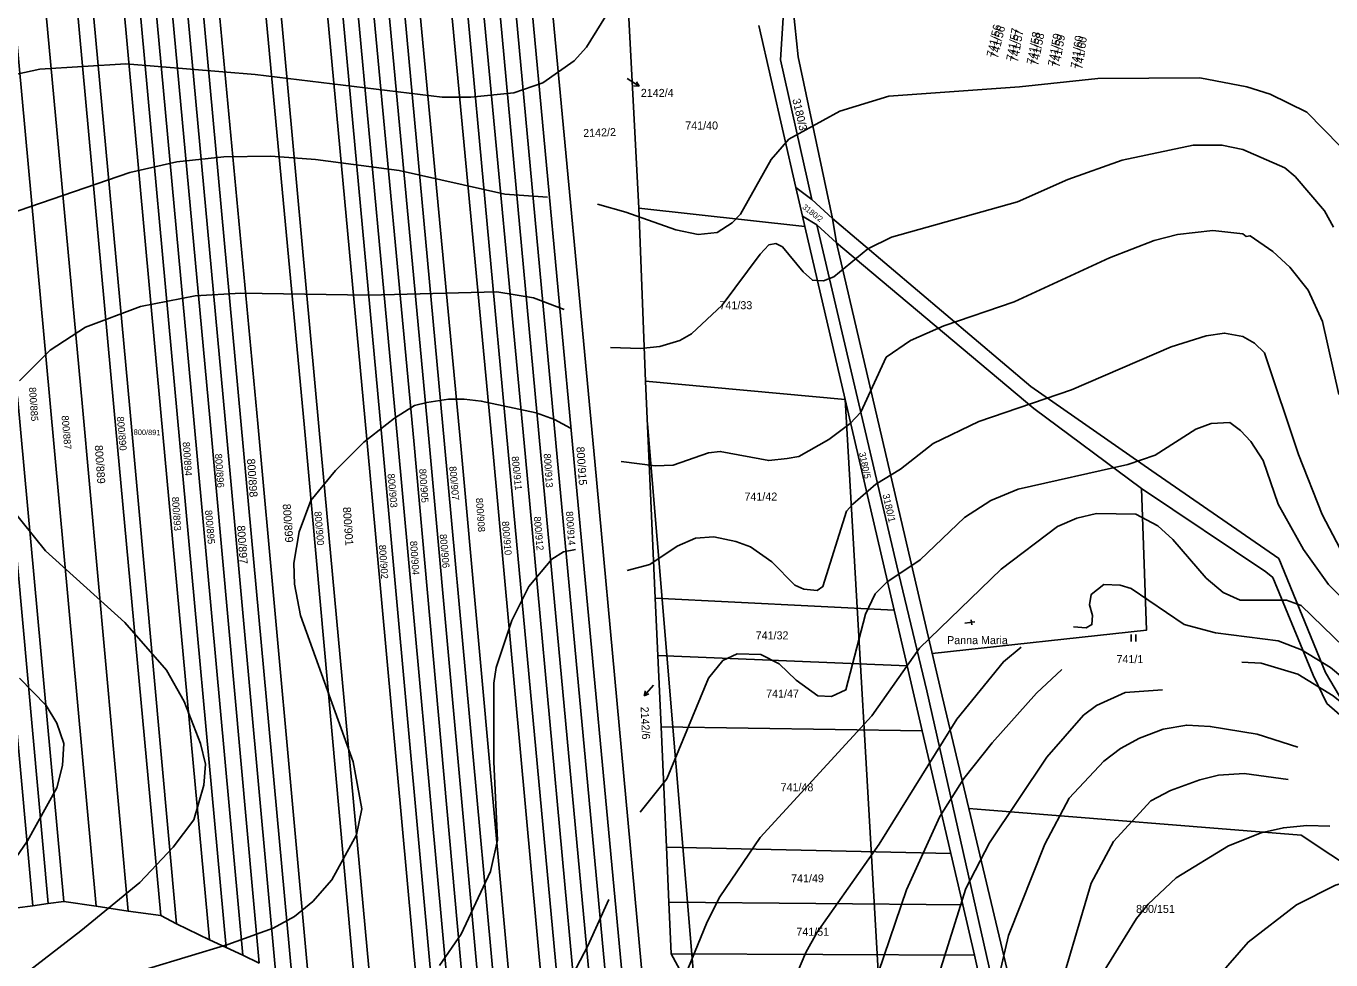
# Model space of a CAD drawing. Extents: x -555860 to -552701, y -1187050 to -1182291.
# Drawn here: x -554447.8 to -554170.8, y -1185774.2 to -1185576 of the extents above; entities that cross this region are included whole.
import ezdxf

# ---------------------------------------------------------------- set-up
doc = ezdxf.new("R2010")
doc.units = 0
for name, color, linetype in [('LEG_2b', 7, 'Continuous'), ('Level 16', 7, 'Continuous'), ('Level 25', 7, 'Continuous'), ('Level 40', 7, 'Continuous'), ('Level 41', 7, 'Continuous'), ('navrh_BV', 7, 'Continuous'), ('Poz předměty', 7, 'Continuous')]:
    doc.layers.add(name, color=color, linetype=linetype)

msp = doc.modelspace()

# ---------------------------------------------------------------- linework, layer by layer
at = {"layer": 'Level 16'}
for p, q in [((-554320.16, -1185587.15), (-554317.65, -1185588.79)), ((-554317.65, -1185588.79), (-554318.21, -1185587.83)), ((-554317.65, -1185588.79), (-554318.76, -1185588.66)), ((-554314.61, -1185715.92), (-554316.57, -1185718.19)), ((-554316.57, -1185718.19), (-554316.3, -1185717.11)), ((-554316.57, -1185718.19), (-554315.54, -1185717.76))]:
    msp.add_line(p, q, dxfattribs=at)
at = {"layer": 'Level 25'}
for p, q in [((-554247.16, -1185702.02), (-554247.02, -1185703.06)), ((-554246.4, -1185702.45), (-554248.48, -1185702.72)), ((-554213.2, -1185706.64), (-554213.2, -1185705.14)), ((-554212.2, -1185706.64), (-554212.2, -1185705.14))]:
    msp.add_line(p, q, dxfattribs=at)
at = {"layer": 'Level 40'}
for points in [[(-554326.49, -1185613.8), (-554320.45, -1185615.5), (-554309.82, -1185619.27), (-554305.11, -1185620.24), (-554301.08, -1185619.8), (-554297.9, -1185617.75), (-554296.1, -1185615.94), (-554289.58, -1185604.3), (-554285.84, -1185600), (-554275.02, -1185594.04), (-554264.62, -1185590.85), (-554236.89, -1185588.91), (-554220.25, -1185587.1), (-554198.62, -1185586.96), (-554188.64, -1185588.91), (-554183.65, -1185590.43), (-554175.88, -1185594.31), (-554168.81, -1185601.52)], [(-554456.52, -1185617.61), (-554425.74, -1185607.07), (-554415.76, -1185604.85), (-554405.77, -1185603.74), (-554395.79, -1185603.6), (-554386.36, -1185604.3), (-554368.61, -1185606.66), (-554346.15, -1185611.65), (-554337.11, -1185612.31)], [(-554165.62, -1185710.09), (-554177.12, -1185699), (-554180.18, -1185697.89), (-554190.02, -1185697.89), (-554193.63, -1185696.23), (-554197.23, -1185693.18), (-554204.31, -1185685), (-554207.49, -1185682.08), (-554212.21, -1185679.59), (-554220.53, -1185679.45), (-554224.69, -1185680.42), (-554228.85, -1185682.22), (-554240.77, -1185691.24), (-554258.1, -1185708.01), (-554268.23, -1185722.43), (-554291.94, -1185748.22), (-554300.53, -1185760.84), (-554303.17, -1185766.11), (-554310.64, -1185784.29)], [(-554451.67, -1185755.02), (-554447.51, -1185748.92), (-554441.27, -1185737.69), (-554440.02, -1185732.97), (-554439.74, -1185728.26), (-554441.27, -1185723.96), (-554443.49, -1185720.22), (-554449.17, -1185714.39)], [(-554233.48, -1185802.27), (-554229.54, -1185784.55), (-554221.64, -1185757.93), (-554216.92, -1185749.06), (-554209.02, -1185740.46), (-554204.82, -1185738.24), (-554198.62, -1185736.02), (-554194.67, -1185735.02), (-554189.19, -1185734.63), (-554179.85, -1185735.92)]]:
    msp.add_lwpolyline(points, dxfattribs=at)
at = {"layer": 'Level 41'}
for points in [[(-554454.03, -1185587.1), (-554444.88, -1185585.16), (-554426.57, -1185584.05), (-554399.12, -1185586.27), (-554359.46, -1185591.12), (-554353.36, -1185591.12), (-554344.21, -1185590.15), (-554338.11, -1185588.07), (-554331.45, -1185583.36), (-554328.82, -1185580.45), (-554321.64, -1185568.86)], [(-554323.69, -1185644.21), (-554317.32, -1185644.47), (-554313.21, -1185644.05), (-554308.99, -1185642.71), (-554306.49, -1185641.32), (-554299.98, -1185635.22), (-554291.94, -1185624.4), (-554290.13, -1185622.46), (-554288.61, -1185622.18), (-554287.22, -1185622.88), (-554282.79, -1185628.15), (-554280.84, -1185629.95), (-554278.49, -1185630.09), (-554276.27, -1185629.26), (-554269.06, -1185623.29), (-554264.07, -1185620.8), (-554237.31, -1185613.31), (-554226.63, -1185608.6), (-554215.12, -1185604.44), (-554200.01, -1185601.25), (-554193.91, -1185601.25), (-554189.47, -1185602.22), (-554180.59, -1185606.1), (-554178.38, -1185607.9), (-554172.14, -1185615.25), (-554170.2, -1185618.72)], [(-554169.09, -1185654.21), (-554172.55, -1185638.68), (-554175.6, -1185632.03), (-554179.48, -1185627.18), (-554183.09, -1185623.85), (-554187.94, -1185620.52), (-554188.78, -1185620.66), (-554189.47, -1185620.1), (-554195.85, -1185619.41), (-554203.33, -1185620.24), (-554208.33, -1185621.49), (-554217.76, -1185625.23), (-554238, -1185634.52), (-554252.97, -1185639.66), (-554260.05, -1185642.71), (-554265.18, -1185646.31), (-554270.58, -1185657.96), (-554272.86, -1185660.39), (-554277.38, -1185663.78), (-554283.76, -1185667.39), (-554286.23, -1185667.81), (-554290.13, -1185668.22), (-554300.4, -1185666.28), (-554302.89, -1185666.55), (-554310.38, -1185669.19), (-554314.26, -1185669.33), (-554321.46, -1185668.45)], [(-554333.54, -1185636.15), (-554340.05, -1185633.69), (-554347.82, -1185632.44), (-554374.99, -1185633.14), (-554402.17, -1185632.72), (-554411.88, -1185633.28), (-554423.52, -1185635.5), (-554435.17, -1185639.93), (-554442.66, -1185644.78), (-554449.17, -1185651.3)], [(-554168.81, -1185686.94), (-554172.66, -1185679.69), (-554177.68, -1185666.97), (-554184.89, -1185645.34), (-554187.02, -1185643.31), (-554189.47, -1185641.87), (-554193.35, -1185641.18), (-554197.23, -1185641.74), (-554204.72, -1185644.09), (-554225.88, -1185653.21), (-554245.49, -1185659.9), (-554255.19, -1185664.61), (-554262.12, -1185670.02), (-554267.39, -1185673.21), (-554272.25, -1185677.51), (-554273.61, -1185678.95), (-554278.62, -1185694.98), (-554279.87, -1185695.81), (-554282.65, -1185695.53), (-554284.59, -1185694.7), (-554289.44, -1185689.71), (-554294.02, -1185686.52), (-554297.12, -1185685.39), (-554301.78, -1185684.44), (-554305.66, -1185684.72), (-554309.55, -1185686.38), (-554315.37, -1185690.27), (-554320.15, -1185691.59)], [(-554430.18, -1185778.59), (-554404.94, -1185770.96), (-554395.32, -1185767.45), (-554390.8, -1185765), (-554386.92, -1185761.81), (-554382.9, -1185757.24), (-554377.63, -1185747.67), (-554376.52, -1185742.12), (-554378.32, -1185732.14), (-554389.55, -1185701.08), (-554390.8, -1185694.43), (-554390.94, -1185689.99), (-554389.83, -1185683.33), (-554387.33, -1185676.68), (-554382.06, -1185670.3), (-554376.1, -1185664.34), (-554369.58, -1185659.21), (-554365.29, -1185656.57), (-554362.72, -1185655.93), (-554358.08, -1185655.18), (-554354.8, -1185655.19), (-554351.14, -1185655.6), (-554339.5, -1185658.1), (-554335.61, -1185659.48), (-554332.18, -1185661.37)], [(-554161.04, -1185704.96), (-554171.31, -1185694.56), (-554176.57, -1185687.07), (-554181.98, -1185677.51), (-554185.17, -1185668.22), (-554187.81, -1185664.2), (-554189.99, -1185661.87), (-554192.24, -1185660.18), (-554196.18, -1185660.39), (-554199.45, -1185661.56), (-554208.05, -1185667.11), (-554213.87, -1185669.05), (-554237.17, -1185674.32), (-554242.99, -1185676.68), (-554248.54, -1185680.28), (-554257.97, -1185689.29), (-554265.04, -1185694.01), (-554267.53, -1185696.5), (-554269.61, -1185700.8), (-554273.77, -1185716.89), (-554276.82, -1185718.27), (-554279.73, -1185718.13), (-554284.31, -1185714.81), (-554287.92, -1185711.34), (-554291.8, -1185709.4), (-554296.79, -1185709.26), (-554299.84, -1185710.65), (-554302.89, -1185714.39), (-554311.76, -1185735.75), (-554317.45, -1185742.82)], [(-554450.98, -1185678.34), (-554443.63, -1185687.35), (-554426.85, -1185702.61), (-554417.98, -1185712.73), (-554414.23, -1185719.38), (-554410.77, -1185728.26), (-554409.66, -1185732.69), (-554410.07, -1185737.13), (-554412.15, -1185744.48), (-554416.59, -1185750.3), (-554423.66, -1185757.79), (-554436.14, -1185768.05), (-554461.79, -1185787.74)], [(-554331.15, -1185687.12), (-554333.67, -1185687.63), (-554336.17, -1185689.16), (-554341.02, -1185694.98), (-554344.63, -1185702.19), (-554347.95, -1185712.17), (-554348.51, -1185715.5), (-554348.51, -1185732.14), (-554347.68, -1185748.78), (-554349.2, -1185755.43), (-554355.44, -1185768.75), (-554360.02, -1185775.4)], [(-554225.39, -1185703.49), (-554222.75, -1185703.71), (-554221.5, -1185703.02), (-554221.36, -1185701.08), (-554222.05, -1185698.86), (-554221.64, -1185696.64), (-554219, -1185694.56), (-554215.54, -1185694.7), (-554213.18, -1185695.39), (-554201.95, -1185703.02), (-554195.29, -1185704.82), (-554181.98, -1185706.49), (-554176.99, -1185708.43), (-554170.89, -1185712.17), (-554162.98, -1185718.69)], [(-554236.51, -1185707.81), (-554240.31, -1185710.91), (-554250.2, -1185723.13), (-554266.7, -1185749.61), (-554279.87, -1185768.33), (-554282.25, -1185772.64), (-554284.03, -1185776.79), (-554287.08, -1185788.43), (-554288.05, -1185795.16), (-554290.41, -1185803.96), (-554297, -1185815.68)], [(-554271.14, -1185791.98), (-554266.84, -1185776.79), (-554260.88, -1185759.32), (-554253.81, -1185743.79), (-554248.68, -1185735.74), (-554242.71, -1185728.12), (-554233.29, -1185717.58), (-554227.88, -1185712.59)], [(-554094.33, -1185743.24), (-554110.16, -1185742.82), (-554130.12, -1185740.32), (-554136, -1185738.98), (-554140.11, -1185737.41), (-554162.43, -1185724.51), (-554170.33, -1185718.13), (-554177.82, -1185713.56), (-554185.59, -1185711.2), (-554189.67, -1185711.01)], [(-554257.85, -1185812.51), (-554256.58, -1185791.48), (-554254.36, -1185778.45), (-554248.26, -1185759.04), (-554243.27, -1185749.33), (-554231.07, -1185731.17), (-554223.3, -1185722.29), (-554220.53, -1185720.21), (-554214.43, -1185717.44), (-554206.52, -1185716.89)], [(-554177.81, -1185729.05), (-554186.42, -1185726.32), (-554196.4, -1185724.65), (-554201.39, -1185724.37), (-554206.39, -1185725.21), (-554211.38, -1185727.15), (-554215.46, -1185729.33), (-554219, -1185732), (-554226.35, -1185739.9), (-554231.48, -1185749.61), (-554239.25, -1185769.02), (-554242.85, -1185784.55), (-554243.96, -1185802.02), (-554242.44, -1185811.73), (-554240.38, -1185821.13)], [(-554171, -1185745.81), (-554175.86, -1185745.67), (-554180.87, -1185746.14), (-554185.59, -1185747.25), (-554192.52, -1185750.03), (-554203.61, -1185756.82), (-554209.57, -1185762.37), (-554212.07, -1185765.42), (-554219.83, -1185778.03), (-554227.05, -1185797.03), (-554229.68, -1185810.2)], [(-554153.21, -1185756.36), (-554164.79, -1185756.96), (-554169.78, -1185758.34), (-554178.1, -1185762.5), (-554188.36, -1185770.41), (-554203.2, -1185787.46), (-554207.91, -1185795.23), (-554217.89, -1185815.05), (-554221.78, -1185828.65), (-554223.86, -1185840.15)], [(-554339.77, -1185792.73), (-554328.54, -1185771.24), (-554324.1, -1185761.4)]]:
    msp.add_lwpolyline(points, dxfattribs=at)
at = {"layer": 'navrh_BV'}
for p, q in [((-554442.73, -1185655.37), (-554456.32, -1185507.52)), ((-554435.84, -1185656.05), (-554449.34, -1185510.8)), ((-554429.16, -1185656.88), (-554442.32, -1185513.98)), ((-554425.76, -1185657.17), (-554438.85, -1185515.59)), ((-554431.88, -1185519.01), (-554419.15, -1185658.02)), ((-554415.69, -1185658.4), (-554428.36, -1185520.6)), ((-554412.22, -1185658.78), (-554424.86, -1185522.18)), ((-554408.77, -1185659.15), (-554421.31, -1185523.93)), ((-554405.55, -1185659.47), (-554417.88, -1185525.56)), ((-554402.2, -1185659.85), (-554414.38, -1185527.07)), ((-554398.56, -1185660.34), (-554410.96, -1185528.75)), ((-554388.66, -1185661.3), (-554400.63, -1185533.72)), ((-554385.55, -1185661.75), (-554397.17, -1185535.37)), ((-554375.51, -1185662.92), (-554386.9, -1185540.22)), ((-554372.25, -1185663.26), (-554383.52, -1185541.8)), ((-554368.92, -1185663.64), (-554380.06, -1185543.41)), ((-554365.49, -1185664.03), (-554376.64, -1185544.98)), ((-554362.22, -1185664.41), (-554373.23, -1185546.71)), ((-554358.93, -1185664.71), (-554369.73, -1185548.36)), ((-554355.48, -1185665.08), (-554366.34, -1185550.02)), ((-554348.7, -1185665.94), (-554359.29, -1185553.31)), ((-554345.41, -1185666.28), (-554355.71, -1185555.08)), ((-554341.84, -1185666.73), (-554352.18, -1185556.68)), ((-554338.49, -1185667.11), (-554348.54, -1185558.46)), ((-554335, -1185667.51), (-554345.01, -1185560.2)), ((-554331.47, -1185667.84), (-554341.34, -1185561.89)), ((-554336.84, -1185563.97), (-554327.06, -1185668.41)), ((-554286.52, -1185566.23), (-554287.62, -1185583.18)), ((-554320.03, -1185570.25), (-554317.73, -1185614.65)), ((-554284.9, -1185572.37), (-554283.87, -1185582.54)), ((-554284.34, -1185610.24), (-554292.21, -1185575.92)), ((-554283.87, -1185582.54), (-554276.6, -1185616.82)), ((-554280.94, -1185612.79), (-554287.62, -1185583.18)), ((-554280.94, -1185612.79), (-554284.34, -1185610.24)), ((-554282.94, -1185616.37), (-554284.34, -1185610.24)), ((-554276.6, -1185616.82), (-554280.94, -1185612.79)), ((-554317.73, -1185614.65), (-554316.26, -1185651.34)), ((-554317.73, -1185614.65), (-554282.43, -1185618.58)), ((-554282.94, -1185616.37), (-554279.92, -1185618.19)), ((-554282.43, -1185618.58), (-554282.94, -1185616.37)), ((-554273.88, -1185655.23), (-554282.43, -1185618.58)), ((-554279.92, -1185618.19), (-554275.71, -1185622.04)), ((-554279.92, -1185618.19), (-554262.9, -1185690.58)), ((-554276.6, -1185616.82), (-554234.45, -1185652.54)), ((-554276.6, -1185616.82), (-554275.71, -1185622.04)), ((-554233.83, -1185657.14), (-554275.71, -1185622.04)), ((-554275.71, -1185622.04), (-554258.42, -1185696.34)), ((-554316.26, -1185651.34), (-554314.2, -1185697.45)), ((-554316.26, -1185651.34), (-554273.88, -1185655.23)), ((-554446.37, -1185762.71), (-554456.28, -1185653.73)), ((-554443.07, -1185762.25), (-554452.87, -1185654.2)), ((-554439.78, -1185761.81), (-554449.57, -1185654.65)), ((-554234.45, -1185652.54), (-554208.82, -1185670.43)), ((-554432.88, -1185762.83), (-554442.73, -1185655.37)), ((-554426.08, -1185763.86), (-554435.84, -1185656.05)), ((-554419.2, -1185764.8), (-554429.16, -1185656.88)), ((-554415.87, -1185766.52), (-554425.76, -1185657.17)), ((-554263.47, -1185700.01), (-554273.88, -1185655.23)), ((-554211.02, -1185674.13), (-554233.83, -1185657.14)), ((-554408.83, -1185769.95), (-554419.15, -1185658.02)), ((-554405.32, -1185771.56), (-554415.69, -1185658.4)), ((-554401.79, -1185773.17), (-554412.22, -1185658.78)), ((-554398.3, -1185774.89), (-554408.77, -1185659.15)), ((-554394.8, -1185776.52), (-554405.55, -1185659.47)), ((-554391.28, -1185778.28), (-554402.2, -1185659.85)), ((-554387.76, -1185779.21), (-554398.56, -1185660.34)), ((-554377.75, -1185782.01), (-554388.66, -1185661.3)), ((-554374.38, -1185782.84), (-554385.55, -1185661.75)), ((-554364.28, -1185785.56), (-554375.51, -1185662.92)), ((-554361.04, -1185786.44), (-554372.25, -1185663.26)), ((-554357.6, -1185787.4), (-554368.92, -1185663.64)), ((-554354.3, -1185788.35), (-554365.49, -1185664.03)), ((-554350.95, -1185788.56), (-554362.22, -1185664.41)), ((-554347.59, -1185788.89), (-554358.93, -1185664.71)), ((-554344.21, -1185789.3), (-554355.48, -1185665.08)), ((-554337.37, -1185790.13), (-554348.7, -1185665.94)), ((-554333.88, -1185790.46), (-554345.41, -1185666.28)), ((-554330.42, -1185790.93), (-554341.84, -1185666.73)), ((-554326.94, -1185791.26), (-554338.49, -1185667.11)), ((-554323.43, -1185791.64), (-554335, -1185667.51)), ((-554319.91, -1185791.94), (-554331.47, -1185667.84)), ((-554327.06, -1185668.41), (-554315.57, -1185792.41)), ((-554208.82, -1185670.43), (-554181.86, -1185689.04)), ((-554184.61, -1185691.85), (-554211.02, -1185674.13)), ((-554262.9, -1185690.58), (-554256.55, -1185717.12)), ((-554181.86, -1185689.04), (-554171.94, -1185713.23)), ((-554183.1, -1185693.05), (-554184.61, -1185691.85)), ((-554174.52, -1185713.8), (-554183.1, -1185693.05)), ((-554258.42, -1185696.34), (-554253.33, -1185718.22)), ((-554314.2, -1185697.45), (-554313.65, -1185709.58)), ((-554314.2, -1185697.45), (-554263.47, -1185700.01)), ((-554260.73, -1185711.78), (-554263.47, -1185700.01)), ((-554313.65, -1185709.58), (-554312.98, -1185724.75)), ((-554313.65, -1185709.58), (-554260.73, -1185711.78)), ((-554257.53, -1185725.59), (-554260.73, -1185711.78)), ((-554171.94, -1185713.23), (-554168.98, -1185718.23)), ((-554171.66, -1185719.81), (-554174.52, -1185713.8)), ((-554256.55, -1185717.12), (-554241.1, -1185785.56)), ((-554253.33, -1185718.22), (-554247.64, -1185742.08)), ((-554164.23, -1185726.28), (-554171.66, -1185719.81)), ((-554312.98, -1185724.75), (-554311.84, -1185750.3)), ((-554312.98, -1185724.75), (-554257.53, -1185725.59)), ((-554251.47, -1185751.65), (-554257.53, -1185725.59)), ((-554237.39, -1185785.09), (-554247.64, -1185742.08)), ((-554247.64, -1185742.08), (-554244.07, -1185742.37)), ((-554244.07, -1185742.37), (-554177.07, -1185747.73)), ((-554177.07, -1185747.73), (-554137.54, -1185774.16)), ((-554311.31, -1185761.98), (-554311.84, -1185750.3)), ((-554311.84, -1185750.3), (-554251.47, -1185751.65)), ((-554251.47, -1185751.65), (-554248.95, -1185762.5)), ((-554449.65, -1185763.12), (-554446.37, -1185762.71)), ((-554446.37, -1185762.71), (-554443.07, -1185762.25)), ((-554443.07, -1185762.25), (-554439.78, -1185761.81)), ((-554432.88, -1185762.83), (-554439.78, -1185761.81)), ((-554426.08, -1185763.86), (-554432.88, -1185762.83)), ((-554310.82, -1185772.95), (-554311.31, -1185761.98)), ((-554311.31, -1185761.98), (-554248.95, -1185762.5)), ((-554248.95, -1185762.5), (-554246.46, -1185773.2)), ((-554426.08, -1185763.86), (-554419.2, -1185764.8)), ((-554419.2, -1185764.8), (-554415.87, -1185766.52)), ((-554408.83, -1185769.95), (-554415.87, -1185766.52)), ((-554408.83, -1185769.95), (-554405.32, -1185771.56)), ((-554405.32, -1185771.56), (-554401.79, -1185773.17)), ((-554401.79, -1185773.17), (-554398.3, -1185774.89)), ((-554246.46, -1185773.2), (-554310.82, -1185772.95)), ((-554303.28, -1185786.68), (-554310.82, -1185772.95)), ((-554246.46, -1185773.2), (-554243.54, -1185785.8))]:
    msp.add_line(p, q, dxfattribs=at)
at = {"layer": 'Poz předměty'}
for points in [[(-554273.88, -1185655.23), (-554266.32, -1185786.4)], [(-554305.65, -1185782.36), (-554315.85, -1185660.44)], [(-554255.43, -1185709.18), (-554209.94, -1185704.25), (-554211.02, -1185674.13)]]:
    msp.add_lwpolyline(points, dxfattribs=at)

# ---------------------------------------------------------------- texts
at = {"layer": 'LEG_2b'}
for s, height, rotation, p in [('741/56', 1.7, 77, (-554241.47, -1185582.98)), ('741/57', 1.7, 80, (-554237.24, -1185583.76)), ('741/58', 1.7, 79, (-554232.92, -1185584.51)), ('741/59', 1.7, 80, (-554228.39, -1185584.85)), ('741/60', 1.7, 82, (-554223.53, -1185585.28)), ('3180/3', 1.7, 283, (-554285.12, -1185591.58)), ('2142/2', 1.7, 2, (-554329.48, -1185599.57)), ('3180/2', 1.2, 322, (-554283.09, -1185614.64)), ('800/885', 1.5, 274, (-554447.18, -1185652.7)), ('800/887', 1.5, 275, (-554440.26, -1185658.73)), ('800/890', 1.5, 275, (-554428.52, -1185658.95)), ('800/891', 1.139, 359, (-554424.95, -1185662.75)), ('800/889', 1.7, 274, (-554433.21, -1185665)), ('800/894', 1.5, 274, (-554414.54, -1185664.31)), ('800/915', 1.7, 274, (-554330.96, -1185665.33)), ('800/896', 1.5, 274, (-554407.7, -1185666.81)), ('800/898', 1.7, 274, (-554400.88, -1185667.87)), ('800/911', 1.5, 276, (-554344.71, -1185667.38)), ('800/913', 1.5, 274, (-554337.9, -1185666.78)), ('3180/5', 1.4, 282, (-554270.97, -1185666.59)), ('800/903', 1.5, 275, (-554371.05, -1185671.06)), ('800/905', 1.5, 274, (-554364.34, -1185670.01)), ('800/907', 1.5, 275, (-554357.95, -1185669.5)), ('800/893', 1.5, 274, (-554416.84, -1185675.97)), ('800/908', 1.5, 274, (-554352.3, -1185676.2)), ('3180/1', 1.5, 283, (-554265.99, -1185675.48)), ('800/895', 1.5, 275, (-554409.8, -1185678.8)), ('800/899', 1.7, 274, (-554393.31, -1185677.48)), ('800/900', 1.5, 275, (-554386.6, -1185679.07)), ('800/901', 1.7, 274, (-554380.54, -1185678.13)), ('800/914', 1.5, 274, (-554333.18, -1185679.03)), ('800/897', 1.7, 274, (-554403, -1185682.05)), ('800/910', 1.5, 275, (-554346.78, -1185681.15)), ('800/912', 1.5, 275, (-554340.01, -1185680.15)), ('800/904', 1.5, 274, (-554366.28, -1185685.33)), ('800/906', 1.5, 275, (-554359.98, -1185683.89)), ('800/902', 1.5, 274, (-554372.89, -1185686.16))]:
    msp.add_text(s, height=height, rotation=rotation, dxfattribs=at).set_placement(p)
for s, p in [('741/40', (-554307.84, -1185597.96)), ('741/33', (-554300.57, -1185636.1)), ('741/42', (-554295.27, -1185676.72)), ('741/32', (-554292.89, -1185706.18)), ('741/1', (-554216.29, -1185711.22)), ('741/47', (-554290.67, -1185718.54)), ('741/48', (-554287.6, -1185738.41)), ('741/49', (-554285.37, -1185757.74)), ('800/151', (-554212.13, -1185764.24)), ('741/51', (-554284.26, -1185769.08))]:
    msp.add_text(s, height=1.7, dxfattribs=at).set_placement(p)
at = {"layer": 'Level 16'}
for s, rotation, p in [('741/56', 77.4, (-554242.26, -1185582.66)), ('741/57', 80.1, (-554238.06, -1185583.44)), ('741/58', 79.2, (-554233.74, -1185584.23)), ('741/59', 80.1, (-554229.21, -1185584.57)), ('741/60', 81.9, (-554224.38, -1185585.02)), ('2142/6', 272.7, (-554317.32, -1185720.5))]:
    msp.add_text(s, height=1.7, rotation=rotation, dxfattribs=at).set_placement(p)
for s, p in [('2142/4', (-554317.27, -1185591.04)), ('Panna Maria', (-554252.26, -1185707.19))]:
    msp.add_text(s, height=1.7, dxfattribs=at).set_placement(p)

doc.saveas('drawing.dxf')
